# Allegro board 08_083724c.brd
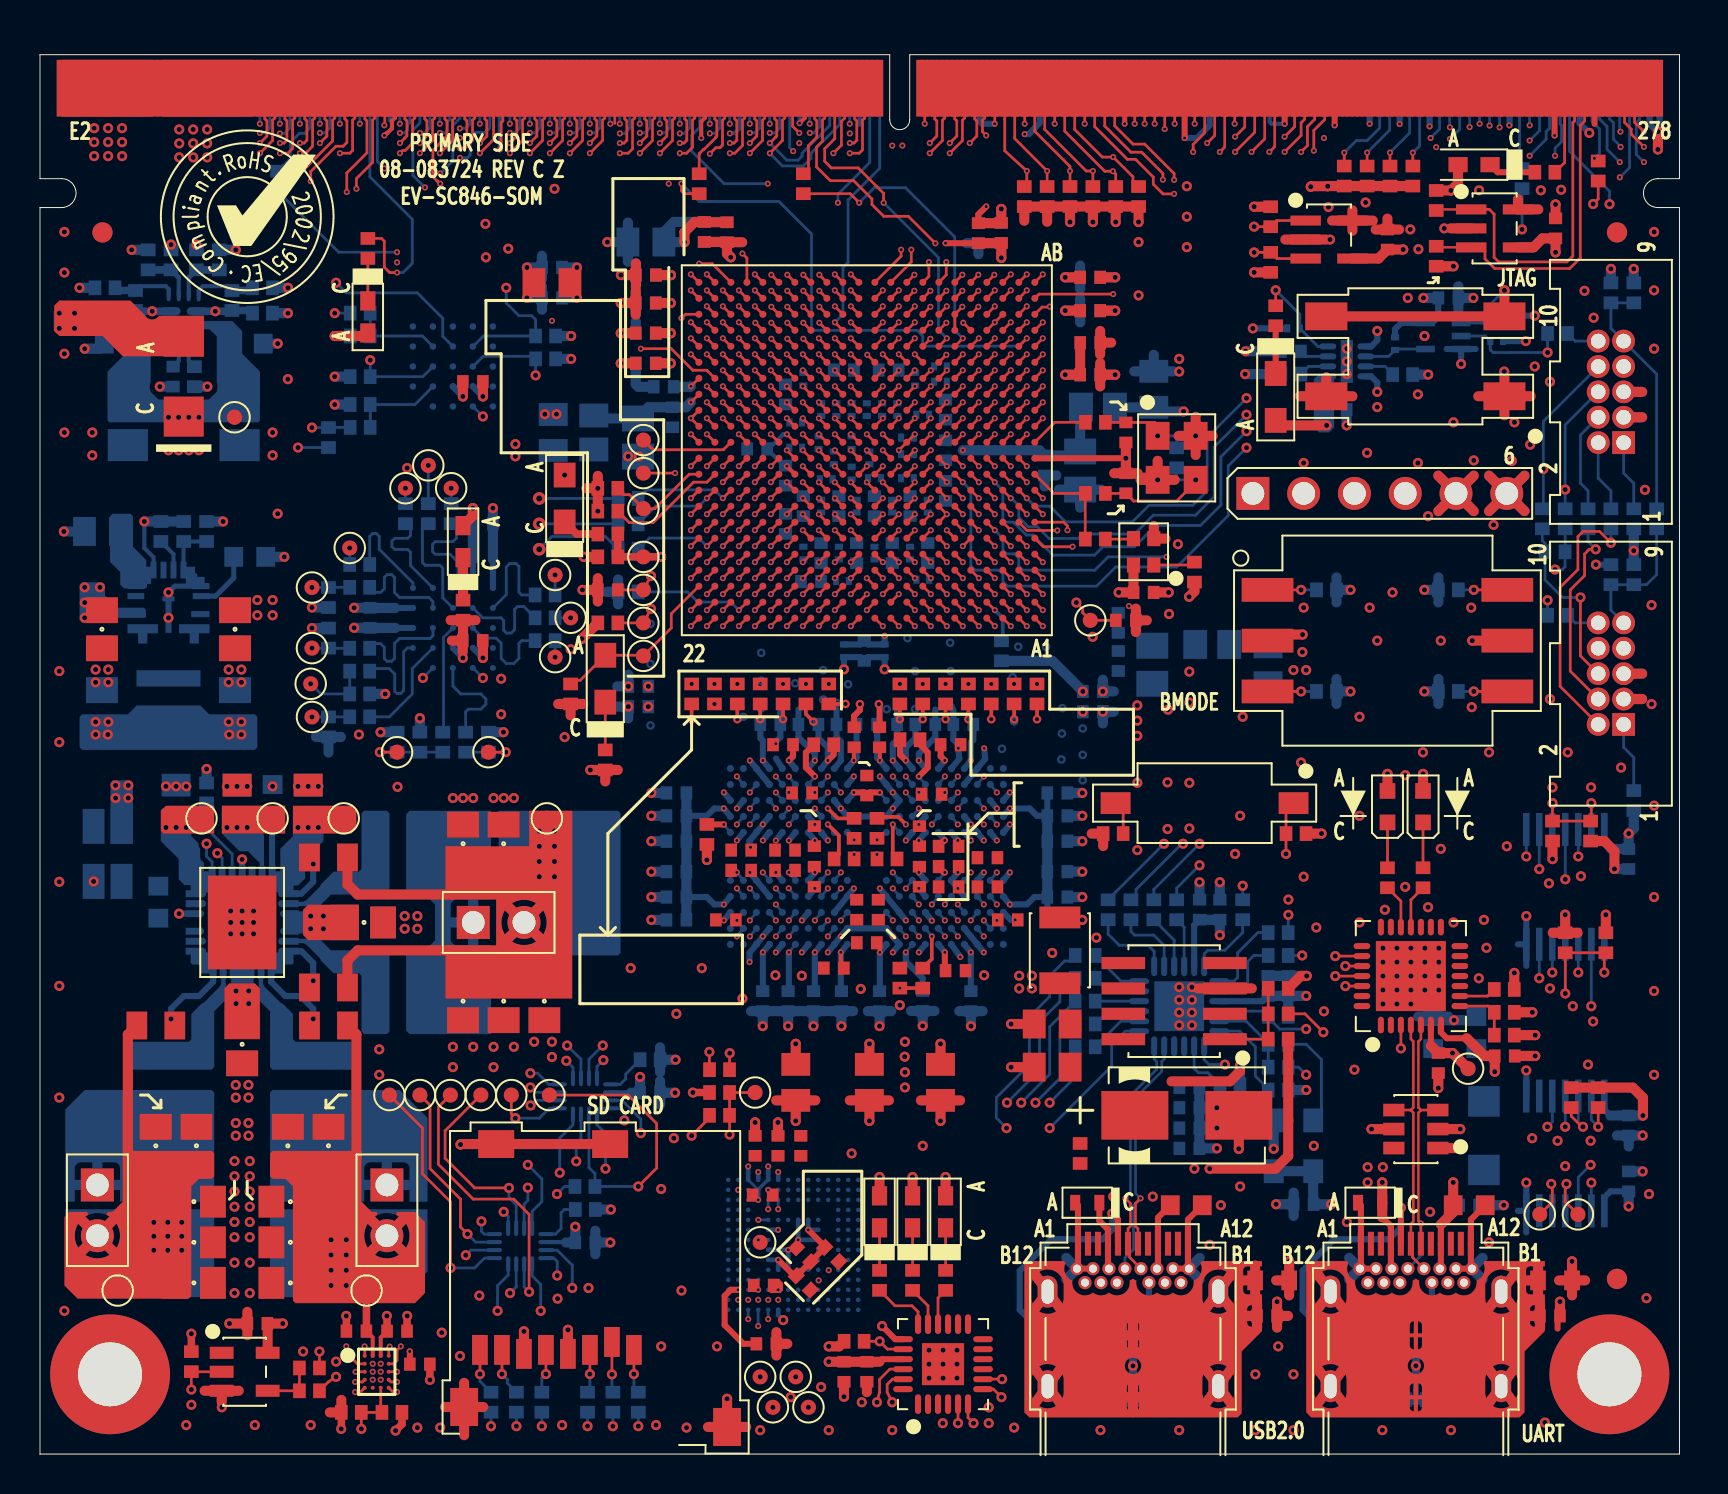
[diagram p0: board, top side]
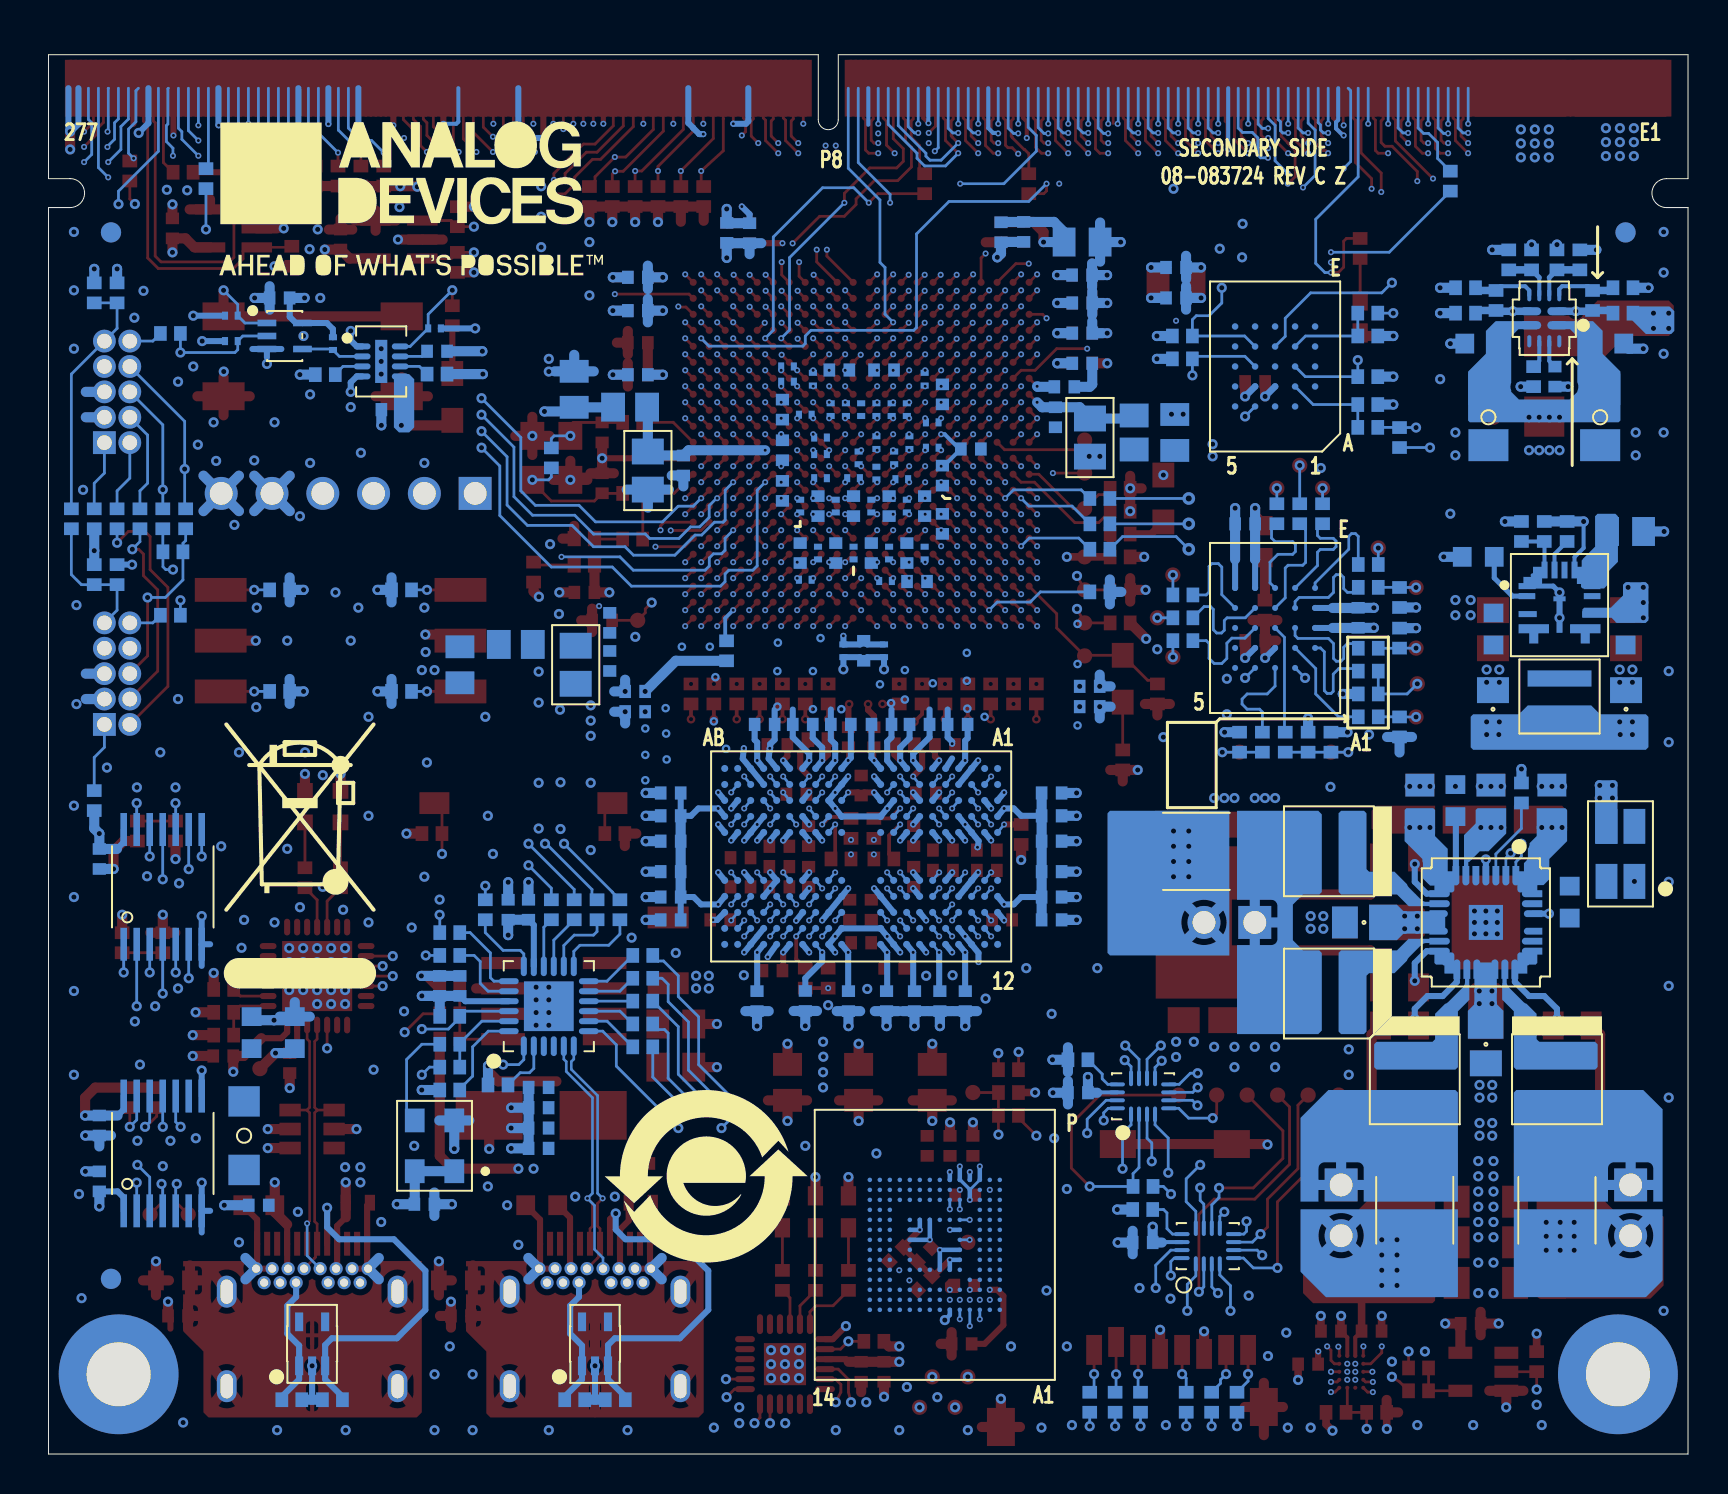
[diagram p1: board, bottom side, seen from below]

Outline 81.99 x 70 mm; copper layers: TOP, L2_GND, L3_SIG1, L4_GND, L5_SIG2, L6_PWR1, L7_PWR2, L8_SIG3, L9_GND, L10_SIG4, L11_GND, BOTTOM. Coordinates in mm from the lower left corner of the outline.
Outline path: 0,70 42.5,70 42.5,66.75 arc(43,66.25) 43.5,66.75 43.5,70 81.99,70 81.99,63.8 80.91,63.8 arc(80.19,63.08) 80.91,62.36 81.99,62.36 81.99,0 0,0 0,62.36 1.08,62.36 arc(1.8,63.08) 1.08,63.8 0,63.8 0,70

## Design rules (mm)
constraint set DEFAULT: min track width 0.14
net group _N89: nets _N89 _N102
net group ADDR-CMD-CLKA: nets CK_T_A CS1_A
net group ADDR_CMD-CLKB: nets CK_T_B CS1_B
net group DP_USB: nets USB_DM USB_DP
net group EMSI0_CLK: nets EMSI0_CLK EMSI0_CLK_X
net group PB_12/TM0_TMR5/SPI5_CLK/PWM0_DH: nets PB_12/TM0_TMR5/SPI5_CLK/PWM0__1 PB_12/TM0_TMR5/SPI5_CLK/PWM0_DH
net group PC_04/SPI2_CLK/TM0_ACLK1: nets PC_04/SPI2_CLK/TM0_ACLK1 PC_04/SPI2_CLK/TM0_ACLK1_X
net group PC_09/SPI0_CLK: nets PC_09/SPI0_CLK PC_09/SPI0_CLK_X
net group PD_12/XSPI0_D2: nets _N562 PD_12/XSPI0_D2
net group PE_11/XSPI1_CLK*: nets _N541 PE_11/XSPI1_CLK*
net group PE_12/XSPI1_CLK/FPLL2_REF_CLK: nets _N544 PE_12/XSPI1_CLK/FPLL2_REF_CLK
net group PF_04/LP0_CLK/FPLL_REF_CLK: nets PF_04/LP0_CLK/FPLL_REF_CLK PF_04/LP0_CLK/FPLL_REF_CLK_X
net group PF_10/LP1_CLK: nets PF_10/LP1_CLK PF_10/LP1_CLK_X
net group PH_10/USB0_STP: nets PH_10/USB0_STP UNNAMED_7_ICUSB331X_I85_STP
net group PH_11/USB0_D7: nets PH_11/USB0_D7 UNNAMED_7_ICUSB331X_I85_DATA7
net group PH_12/USB0_D6: nets PH_12/USB0_D6 UNNAMED_7_ICUSB331X_I85_DATA6
net group PH_13/USB0_D5: nets PH_13/USB0_D5 UNNAMED_7_ICUSB331X_I85_DATA5
net group PH_14/USB0_D4: nets PH_14/USB0_D4 UNNAMED_7_ICUSB331X_I85_DATA4
net group PH_15/USB0_NXT: nets PH_15/USB0_NXT UNNAMED_7_ICUSB331X_I85_NXT
net group PI_00/USB0_DIR: nets PI_00/USB0_DIR UNNAMED_7_ICUSB331X_I85_DIR
net group PI_01/USB0_D3: nets PI_01/USB0_D3 UNNAMED_7_ICUSB331X_I85_DATA3
net group PI_02/USB0_D2: nets PI_02/USB0_D2 UNNAMED_7_ICUSB331X_I85_DATA2
net group PI_03/USB0_D1: nets PI_03/USB0_D1 UNNAMED_7_ICUSB331X_I85_DATA1
net group PI_04/USB0_D0: nets PI_04/USB0_D0 UNNAMED_7_ICUSB331X_I85_DATA0
net group USB_PHY: nets USB_PHY_DM USB_PHY_DP
net group USB_PHY_VBUS_EN: nets UNNAMED_7_ICMIC20X5_I8_EN USB_PHY_VBUS_EN
net group CLKA-STB: nets CK_C_A DQS0_C_A DQS1_C_A
net group CLKB-STB: nets CK_C_B DQS0_C_B DQS1_C_B
net group EMSI0_RST*: nets _N244 EMSI0_RST* SYS_HWRST*
net group GRP_A0: nets DMI0_A DQ0_A DQ1_A DQ2_A DQ3_A DQ4_A DQ5_A DQ6_A DQ7_A DQS0_T_A
net group GRP_A1: nets DMI1_A DQ8_A DQ9_A DQ10_A DQ11_A DQ12_A DQ13_A DQ14_A DQ15_A DQS1_T_A
net group GRP_B0: nets DMI0_B DQ0_B DQ1_B DQ2_B DQ3_B DQ4_B DQ5_B DQ6_B DQ7_B DQS0_T_B
net group GRP_B1: nets DMI1_B DQ8_B DQ9_B DQ10_B DQ13_B DQ14_B DQ15_B DQS1_T_B
net group PC_15/SPI1_CLK/TRACE0_CLK/TM0_A: nets _N82 PC_15/SPI1_CLK/TRACE0_CLK/TM0_1 PC_15/SPI1_CLK/TRACE0_CLK/TM0_A
net group PD_14/XSPI0_CLK/TM0_ACLK4: nets _N558 PD_14/XSPI0_CLK/TM0_ACLK4 PD_14/XSPI0_CLK/TM0_ACLK4_X
net group SYS_CLKIN0: nets _N15 _N16 _N410 SYS_CLKIN0 SYS_XTAL0
net group USB_PHY_REFCLK: nets PI_05/USB0_CLK UNNAMED_7_RES_I185_N1 USB_PHY_CLKOUT USB_PHY_REFCLK
net group USB_PHY_VBUS: nets UNNAMED_7_ICUSB331X_I85_VBUS

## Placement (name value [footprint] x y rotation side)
C1  0.1uF  [C0402]  45.79 24.18 180 top
C2  0.1uF  [C0402]  43.98 28.88 270 top
C3  0.1uF  [C0402]  37.41 22.66 90 bottom
C4  0.1uF  [C0402]  38.72 28.88 270 top
C5  10uF  [C0805H55]  41.48 18.59 270 top
C6  0.1uF  [C0402]  43.98 30.91 90 top
C7  0.1uF  [C0402]  45.54 35.48 180 top
C8  0.1uF  [C0402]  37.16 35.48 0 top
C9  0.1uF  [C0402]  38.72 30.91 90 top
C10  0.1uF  [C0402]  48.4 26.72 180 top
C11  0.1uF  [C0402]  41.35 25.58 0 top
C12  0.1uF  [C0402]  45.44 30.4 180 top
C13  0.1uF  [C0402]  44.59 33.01 0 top
C14  10uF  [C0805H55]  37.8 18.59 270 top
C15  0.1uF  [C0402]  47.38 28.37 180 top
C16  0.1uF  [C0402]  41.99 35.86 270 top
C17  0.1uF  [C0402]  39.7 24.31 0 top
C18  0.1uF  [C0402]  40.72 35.86 270 top
C19  0.1uF  [C0402]  38.11 33.07 180 top
C20  0.1uF  [C0402]  45.44 28.37 180 top
C21  0.1uF  [C0402]  38.43 36.5 0 bottom
C22  0.1uF  [C0402]  40.34 36.5 0 bottom
C23  0.1uF  [C0402]  42.37 36.5 180 bottom
C24  27pF  [C0402]  54.31 48.56 90 top
C25  27pF  [C0402]  54.31 51.1 270 top
C26  10uF  [C0805H53]  52.02 49.2 270 bottom
C27  0.1uF  [C0402]  50.24 49.45 270 bottom
C28  10uF  [C0805H53]  29.91 50.85 270 bottom
C29  0.1uF  [C0402]  31.64 51.87 270 bottom
C30  10uF  [C0805H53]  55.63 39.48 270 bottom
C31  0.1uF  [C0402]  53.92 39.67 270 bottom
C32  0.1uF  [C0402]  10.87 6.53 0 top
C33  0.1uF  [C0402]  28.4 43.23 0 top
C34  0.47uF  [C0402]  30.29 57.58 180 bottom
C35  1uF  [C0402]  29.92 38.4 180 bottom
C36  1uF  [C0402]  52.65 38.15 0 bottom
C37  0.1uF  [C0402]  54.31 41.71 180 top
C38  0.22uF  [C0201]  44.4 47.42 90 bottom
C39  0.22uF  [C0201]  42.62 47.42 90 bottom
C40  0.1uF  [C0402]  43.51 47.42 90 bottom
C41  0.1uF  [C0402]  41.73 47.42 90 bottom
C42  0.22uF  [C0201]  40.84 47.42 90 bottom
C43  0.22uF  [C0201]  39.07 47.42 90 bottom
C44  0.22uF  [C0201]  41.73 45.07 90 bottom
C45  0.22uF  [C0201]  38.18 45.07 90 bottom
C46  0.22uF  [C0201]  42.24 40.18 270 bottom
C47  0.22uF  [C0201]  44.15 43.74 0 bottom
C48  0.22uF  [C0201]  40.13 43.68 0 bottom
C49  0.22uF  [C0201]  40.21 40.18 270 bottom
C50  0.1uF  [C0402]  44.27 36.5 180 bottom
C51  0.1uF  [C0402]  46.18 36.5 0 bottom
C52  0.1uF  [C0402]  50.88 33.07 180 bottom
C53  0.1UF  [C0402]  41.35 4.11 270 top
C54  0.1uF  [C0402]  21.64 40.69 0 top
C55  0.01UF  [C0402]  40.21 4.11 270 top
C56  0.1uF  [C0402]  16.5 41.83 90 bottom
C57  0.1uF  [C0402]  22.15 46.53 180 bottom
C58  0.1uF  [C0402]  21.65 53.64 0 top
C59  0.1UF  [C0402]  30.51 18.07 0 bottom
C60  0.1UF  [C0402]  27.27 10.58 0 bottom
C61  0.1uF  [C0402]  17.86 6.15 180 top
C62  0.1uF  [C0402]  15.82 6.15 0 top
C63  1uF  [C0402]  38.19 9.97 135 top
C64  1uF  [C0402]  36.33 5.51 180 top
C65  0.1uF  [C0402]  39.6 9.98 135 top
C66  2.2uF  [C0402]  19 4.5 0 top
C67  0.1uF  [C0402]  38.18 8.56 135 top
C68  0.1uF  [C0402]  36.2 8.43 0 top
C69  0.1uF  [C0402]  35.76 15.42 270 top
C70  0.1uF  [C0402]  36.14 12.95 180 top
C71  0.1uF  [C0402]  36.91 15.42 270 top
C72  1uF  [C0402]  38.05 15.42 90 top
C86  0.1uF  [C0402]  71.48 12.45 0 bottom
C87  0.01uF  [C0402]  79.45 29.77 270 bottom
C88  4.7uF  [C0603]  71.83 21.08 90 bottom
C89  0.1uF  [C0402]  73.25 19.91 0 top
C90  0.1uF  [C0402]  79.45 13.64 90 bottom
C91  0.1uF  [C0402]  79.45 16.43 270 bottom
C92  4.7uF  [C0603]  69.67 21.08 90 bottom
C93  0.1uF  [C0402]  69.93 19.56 270 top
C94  4.7uF  [C0603]  71.48 12.45 0 top
C95  0.01uF  [C0402]  75.51 6.91 0 top
C96  0.1UF  [C0402]  75.79 61.32 90 top
C97  4.7uF  [C0805H60]  3.1 41.26 270 top
C98  0.1uF  [C0402]  50.88 31.93 180 bottom
C99  0.22uF  [C0201]  39.95 45.07 90 bottom
C100  0.1uF  [C0402]  50.88 30.66 180 bottom
C101  0.1uF  [C0402]  50.88 26.72 180 bottom
C102  0.1uF  [C0402]  50.88 27.86 180 bottom
C103  0.1uF  [C0402]  50.88 29.13 180 bottom
C104  0.1uF  [C0402]  45.44 29.39 180 top
C105  0.22uF  [C0201]  43.51 45.07 90 bottom
C106  0.1uF  [C0402]  39.95 47.42 90 bottom
C107  4.7uF  [C0805H60]  9.75 41.26 270 top
C108  0.1uF  [C0402]  41.92 27.23 270 top
C109  0.1uF  [C0402]  38.18 47.42 90 bottom
C110  0.1uF  [C0402]  42.62 45.07 90 bottom
C111  0.1uF  [C0402]  39.07 45.07 90 bottom
C112  0.1uF  [C0402]  47.38 29.83 180 top
C113  0.1uF  [C0402]  29.92 37.39 180 bottom
C114  0.1uF  [C0402]  37.26 30.21 0 top
C115  0.1uF  [C0402]  41.22 40.18 270 bottom
C116  0.1uF  [C0402]  38.56 43.65 180 bottom
C117  0.1uF  [C0402]  41.35 33.44 270 top
C118  0.1uF  [C0402]  35.06 29.2 180 top
C119  22UF  [C0805H60]  3.1 37.26 270 bottom
C120  0.1uF  [C0402]  52.65 37.13 0 bottom
C121  22UF  [C0805H60]  9.75 37.26 270 bottom
C122  0.1uF  [C0402]  40.84 45.07 90 bottom
C123  10uF  [C0805H55]  9.86 32.56 90 top
C124  10uF  [C0805H55]  9.86 32.56 90 bottom
C125  0.01uF  [C0402]  70.43 57.84 0 bottom
C126  1uF  [C0603]  11.63 32.69 90 bottom
C127  2.2NF  [C0402]  62.56 55.17 180 bottom
C128  4.7uF  [C1206H71]  4.39 51.87 270 bottom
C129  0.1uF  [C0603]  4.01 55.55 180 bottom
C130  0.1uF  [C0402]  44.4 45.07 90 bottom
C131  0.1uF  [C0402]  45.29 52.25 270 bottom
C132  0.1uF  [C0402]  45.29 48.18 270 bottom
C133  0.1uF  [C0402]  37.29 53.01 90 bottom
C134  0.1uF  [C0402]  37.29 46.53 270 bottom
C135  4.7uF  [C1206H71]  9.98 51.87 270 bottom
C136  0.1uF  [C0603]  10.36 55.55 0 bottom
C137  0.01uF  [C0402]  64.85 52.25 0 bottom
C138  10uF  [C0805H55]  13.41 32.56 90 top
C139  4.7uF  [C0805H60]  16.21 26.59 0 bottom
C140  10uF  [C0805H55]  6.81 32.56 90 bottom
C141  4.7uF  [C0805H60]  16.21 26.59 0 top
C142  4.7uF  [C0805H60]  10.11 20.5 270 bottom
C143  4.7uF  [C0805H60]  10.11 20.5 270 top
C144  22UF  [C0805H60]  21.16 22.66 270 top
C145  0.1uF  [C0402]  35.06 30.21 180 top
C146  10uF  [C0805H55]  45.03 18.59 270 top
C147  0.1uF  [C0402]  34.3 26.72 0 top
C148  0.1uF  [C0402]  40.84 27.23 270 top
C149  0.1uF  [C0402]  37.26 29.2 0 top
C150  0.1uF  [C0402]  46.56 22.66 90 bottom
C151  0.1uF  [C0402]  44.15 22.66 90 bottom
C152  0.1uF  [C0402]  41.99 22.66 90 bottom
C153  0.1uF  [C0402]  40.08 22.66 90 bottom
C154  0.1uF  [C0402]  38.68 22.66 90 bottom
C155  0.1uF  [C0402]  36.14 22.66 90 bottom
C156  0.1uF  [C0402]  31.83 26.72 0 bottom
C157  0.1uF  [C0402]  31.83 27.86 0 bottom
C158  0.1uF  [C0402]  31.83 29.13 0 bottom
C159  0.1uF  [C0402]  31.83 30.66 0 bottom
C160  0.1uF  [C0402]  31.83 31.93 0 bottom
C161  0.1uF  [C0402]  31.83 33.07 0 bottom
C162  0.1uF  [C0402]  36.53 36.5 180 bottom
C163  0.1uF  [C0402]  40.21 54.23 180 bottom
C164  10uF  [C0805H55]  55.7 53.26 90 bottom
C165  10uF  [C0805H55]  61.42 39.48 270 bottom
C166  10uF  [C0805H55]  25.67 51.1 90 bottom
C167  0.47uF  [C0402]  45.29 50.22 270 bottom
C168  0.47uF  [C0402]  37.29 48.95 270 bottom
C169  0.47uF  [C0402]  42.44 54.23 180 bottom
C170  0.47uF  [C0402]  35.86 50.28 180 bottom
C171  0.47uF  [C0402]  31.19 53.39 180 bottom
C172  0.22uF  [C0201]  41.35 52.25 270 bottom
C173  0.22uF  [C0201]  45.03 54.41 0 bottom
C174  0.22uF  [C0201]  38.18 53.77 90 bottom
C175  0.22uF  [C0201]  40.59 52.25 270 bottom
C176  0.22uF  [C0201]  39.83 52.25 270 bottom
C177  0.22uF  [C0201]  39.07 52.25 270 bottom
C178  0.22uF  [C0201]  38.94 50.6 270 bottom
C179  0.22uF  [C0201]  39.7 49.83 90 bottom
C180  0.22uF  [C0201]  39.32 48.77 0 bottom
C181  0.22uF  [C0201]  37.8 51.61 180 bottom
C182  0.22uF  [C0201]  37.8 50.34 180 bottom
C183  0.22uF  [C0201]  40.59 50.6 270 bottom
C184  0.1uF  [C0402]  33.22 61.14 270 top
C185  0.1uF  [C0402]  52.52 58.87 180 top
C186  0.1uF  [C0402]  52.52 57.2 180 top
C187  0.1uF  [C0402]  34.36 61.12 270 top
C188  0.1uF  [C0402]  52.52 53.99 0 top
C189  0.1uF  [C0402]  48.07 61.09 270 top
C190  0.1uF  [C0402]  46.93 61.07 270 top
C191  0.1uF  [C0402]  52.52 55.6 0 top
C192  0.1uF  [C0402]  30.29 54.57 180 top
C193  0.1uF  [C0402]  30.29 56.07 180 top
C194  0.1uF  [C0402]  30.29 57.58 180 top
C195  0.1uF  [C0402]  25.6 59.36 180 bottom
C196  1uF  [C0402]  30.3 58.98 180 bottom
C197  1uF  [C0402]  25.6 57.84 180 bottom
C198  10uF  [C0805H55]  30.3 60.63 180 bottom
C199  10uF  [C0805H55]  25.6 58.6 180 top
C200  0.47uF  [C0402]  33.22 61.14 270 bottom
C201  0.47uF  [C0402]  52.52 58.87 180 bottom
C202  0.47uF  [C0402]  52.52 57.2 180 bottom
C203  0.47uF  [C0402]  34.36 61.12 270 bottom
C204  0.47uF  [C0402]  52.52 53.99 0 bottom
C205  0.47uF  [C0402]  46.93 61.07 270 bottom
C206  0.47uF  [C0402]  30.3 58.98 180 top
C207  0.47uF  [C0402]  48.07 61.09 270 bottom
C208  0.47uF  [C0402]  30.29 54.57 180 bottom
C209  0.47uF  [C0402]  30.29 56.07 180 bottom
C210  0.01uF  [C0201]  45.03 53.64 0 bottom
C211  0.01uF  [C0201]  41.48 49.83 90 bottom
C212  0.01uF  [C0201]  40.59 49.07 90 bottom
C213  0.01uF  [C0201]  41.73 48.82 0 bottom
C214  0.01uF  [C0201]  43.38 48.82 180 bottom
C215  0.01uF  [C0201]  43.38 50.03 0 bottom
C216  0.01uF  [C0201]  43.38 50.85 180 bottom
C217  0.01uF  [C0201]  44.15 51.99 180 bottom
C218  0.01uF  [C0201]  42.11 52.25 270 bottom
C219  0.01uF  [C0201]  42.88 52.25 270 bottom
C220  0.01uF  [C0201]  43.76 53.77 90 bottom
C221  22UF  [C0805H60]  25.22 22.66 270 top
C222  22UF  [C0805H60]  23.19 30.53 90 top
C223  22UF  [C0805H60]  23.19 22.66 270 top
C224  22UF  [C0805H60]  21.16 30.53 90 top
C225  22UF  [C0805H60]  7.7 10.59 0 top
C226  22UF  [C0805H60]  12.52 12.62 180 top
C227  22UF  [C0805H60]  7.7 12.62 0 top
C228  22UF  [C0805H60]  12.4 15.42 90 top
C229  22UF  [C0805H60]  5.79 15.42 90 top
C230  22UF  [C0805H60]  12.52 10.59 180 top
C231  22UF  [C0805H60]  7.82 15.42 90 top
C232  22UF  [C0805H60]  12.52 8.56 180 top
C233  22UF  [C0805H60]  7.7 8.56 0 top
C234  10uF  [C0805H55]  13.41 32.56 90 bottom
C235  1uF  [C0603]  5.92 27.61 270 bottom
C236  22UF  [C0805H60]  14.43 15.42 90 top
C237  0.1uF  [C0603]  10.49 44.88 0 bottom
C238  2.2uF  [C0805]  3.12 46.15 180 bottom
C239  1uF  [C0603]  9.73 41.27 270 bottom
C240  1uF  [C0603]  3.12 41.27 270 bottom
C241  0.1uF  [C0402]  55.19 43.1 180 top
C242  0.1UF  [C0402]  67.39 60.76 90 top
C243  1uF  [C0805]  50.62 21.51 180 top
C244  1uF  [C0805]  50.62 19.35 180 top
C245  1uF  [C0402]  53.92 41.58 90 bottom
C246  150UF  [C7343-31-2]  57.35 16.94 0 top
C247  22uF  [C1210H106]  51 25.2 90 top
C248  0.1UF  [C0402]  57.48 16.31 0 bottom
C249  0.01UF  [C0402]  57.48 18.34 0 bottom
C250  1uF  [C0402]  6.65 53.9 270 bottom
C251  0.1UF  [C0402]  57.48 15.29 0 bottom
C252  0.01UF  [C0402]  57.48 17.32 0 bottom
C253  0.1UF  [C0402]  62.43 23.42 90 bottom
C254  0.01UF  [C0402]  61.42 23.42 90 bottom
C255  0.1UF  [C0402]  59 27.23 90 bottom
C256  0.01UF  [C0402]  57.99 27.23 90 bottom
C257  4.7uF  [C0603]  57.33 12.45 0 top
C258  0.01uF  [C0402]  61.37 6.91 0 top
C262  0.1UF  [C0402]  63.2 12.5 180 bottom
D1  ESDA6V1SC6Y  [SOT23_6-3]  68.81 16.26 90 top
D2  ESDA25W5  [SC70-5_A]  68.81 5.51 180 bottom
D3  ESDA25P35-1U1M  [DFN2_1_6X1]  66.52 12.57 180 top
D6  ESDA25W5  [SC70-5_A]  54.66 5.51 180 bottom
D7  RBR5L30BDDTE25  [DO214ACH87]  7.19 53.9 90 top
D8  ESDA25P35-1U1M  [DFN2_1_6X1]  52.37 12.57 180 top
DS1  SML-LX0805SRC-TR  [LED0805_A]  26.24 47.8 90 top
DS2  5988E30107F  [LED0603]  41.99 12.12 90 top
DS3  5988E30107F  [LED0603]  43.64 12.12 90 top
DS4  5988E30107F  [LED0603]  45.29 12.12 90 top
DS5  5988E30107F  [LED0603]  16.4 56.88 270 top
DS6  5988E30107F  [LED0603]  21.16 45.64 90 top
DS7  LY L296-Q2R2-26-Z  [LED0603-2]  69.17 32.39 90 top
DS8  LY L296-Q2R2-26-Z  [LED0603-2]  67.39 32.39 90 top
DS9  5988E30107F  [LED0603]  71.72 64.5 180 top
DS10  SML-LX0805SRC-TR  [LED0805_A]  28.27 38.79 90 top
DS11  SML-LX0805SRC-TR  [LED0805_A]  61.8 52.88 270 top
E1  600OHM  [L1206]  72.21 15.93 90 bottom
E2  100OHM AT 100MHZ  [L0805]  58.62 40.5 0 bottom
E3  100OHM AT 100MHZ  [L0805]  52.91 52.37 0 bottom
E4  100OHM AT 100MHZ  [L0805]  27.7 51.1 270 bottom
JP1  0  [R0402]  75.9 56.06 0 bottom
JP2  0  [R0402]  79.71 46.79 90 bottom
JP3  0  [R0402]  76.28 46.79 90 bottom
JP4  0  [R0402]  78.56 46.79 90 bottom
JP5  0  [R0402]  77.42 46.79 90 bottom
JP6  0  [R0402]  80.85 46.79 90 bottom
JP7  0  [R0402]  75.13 46.79 90 bottom
JP8  0  [R0402]  75.77 45.14 180 bottom
L1  0.68UH  [LSML126W138H118]  6.43 37.9 270 bottom
L2  0.47UH  [LSMSQ157H122]  17.96 30.15 0 bottom
L3  1.5UH  [LSMSQ157H122]  6.55 18.75 270 bottom
L4  1.5UH  [LSMSQ157H122]  13.67 18.75 270 bottom
L5  0.47UH  [LSMSQ157H122]  17.96 23.04 0 bottom
NOREF  -  []  136.5 171.56 0 top
NOREF#2  -  []  3.51 3.99 0 top
NOREF#3  -  []  136.5 152.96 90 top
NOREF#4  -  []  0 0 0 top
NOREF#5  -  []  3.51 3.99 0 top
NOREF#6  -  []  -102.51 -164.11 0 top
NOREF#7  -  [unnamed#2]  78.49 3.99 0 top
NOREF#8  -  []  177.46 55.98 0 top
NOREF#9  -  []  65.03 171.56 0 top
NOREF#10  -  []  0 70 270 top
NOREF#11  -  []  132.9 171.57 0 top
NOREF#12  -  []  285.91 345.58 0 top
NOREF#13  -  []  136.5 156.57 0 top
NOREF#14  -  []  65.03 144.45 90 top
NOREF#15  -  []  0 62.36 0 top
NOREF#16  -  [unnamed#2]  78.87 61.11 90 top
NOREF#17  -  []  168.25 174.35 0 top
NOREF#18  -  []  0 0 0 top
NOREF#19  -  []  53.95 54.84 0 top
NOREF#20  -  []  168.25 154.03 0 top
NOREF#21  -  []  65.03 171.56 0 top
NOREF#22  -  []  -200.3 -242.85 0 top
NOREF#23  -  []  60.03 70 0 top
NOREF#24  -  []  81.99 70 180 top
NOREF#25  -  []  0 70 0 top
NOREF#26  -  [unnamed#2]  3.51 3.99 0 top
NOREF#27  -  []  79.48 -98.58 0 top
NOREF#28  -  []  81.99 0 0 top
NOREF#29  -  []  81.99 0 90 top
NOREF#30  -  []  -32.74 135.53 0 top
NOREF#31  -  []  0 70 0 top
NOREF#32  -  []  -102.51 -164.11 0 top
NOREF#33  -  []  -8.66 -88.93 0 top
NOREF#34  -  []  65.03 152.96 90 top
NOREF#35  -  [unnamed#2]  78.87 8.76 90 top
NOREF#36  -  [unnamed#2]  3.12 61.11 0 top
NOREF#37  -  []  72.23 -93.36 0 top
NOREF#38  -  []  0 70 0 top
NOREF#39  -  []  143.93 112.43 0 top
NOREF#40  -  []  -102.51 -164.11 0 top
NOREF#41  -  []  81.99 0 90 top
NOREF#42  -  []  81.99 0 90 top
NOREF#43  -  []  43.5 70 0 top
NOREF#44  -  []  -19.14 -94.32 0 top
NOREF#45  -  []  -102.51 -164.11 0 top
NOREF#46  -  []  0 0 0 top
NOREF#47  -  []  -26.83 168.28 90 top
NOREF#48  -  []  10.36 61.9 0 top
NOREF#49  -  []  63.83 62.79 180 bottom
NOREF#50  -  []  60.15 40.18 180 bottom
NOREF#51  -  [unnamed#2]  78.87 8.76 270 bottom
NOREF#52  -  [unnamed#2]  78.87 61.11 180 bottom
NOREF#53  -  []  49.1 13.89 180 bottom
NOREF#54  -  [unnamed#2]  3.12 61.11 180 bottom
P2  632723300011  [CNWURTH632723300011]  68.81 5.94 0 top
P3  632723300011  [CNWURTH632723300011]  54.66 5.94 0 top
P4  SHF-105-01-L-D-TH-TR  [CNTHMHDR2X5L500W200H215]  79.2 36.5 90 top
P5  SHF-105-01-L-D-TH-TR  [CNTHMHDR2X5L500W200H215]  79.2 50.6 90 top
P6  693071010811  [CNWURTH693071010811]  27.76 8.31 0 top
P7  TSW-102-08-G-S  [CNSAMTEC1X2H330LD36]  22.94 26.59 0 top
P8  NCFINGER274P_E4P  [FINGER274P_E4P]  43 68.33 0 top
P9  TSW-102-08-G-S  [CNSAMTEC1X2H330LD36]  2.87 12.19 270 top
P10  TSW-102-08-G-S  [CNSAMTEC1X2H330LD36]  17.35 12.19 270 top
P12  TSW-106-08-G-S  [CNBERG1X6H205LD36]  60.66 48.06 0 top
R1  10K  [R0402]  64.34 43.23 0 bottom
R2  10K  [R0402]  70.43 38.15 180 bottom
R3  10K  [R0402]  64.34 38.15 0 bottom
R4  0  [R0402]  79.71 32.69 90 bottom
R5  0  [R0402]  75.9 41.96 0 bottom
R6  10K  [R0402]  70.43 43.23 180 bottom
R7  10  [R0402]  28.4 46.02 0 top
R8  10K  [R0402]  28.4 44.88 0 top
R9  10K  [R0402]  28.4 41.58 0 top
R10  10K  [R0402]  79.71 43.99 270 bottom
R11  0  [R0402]  28.4 48.31 180 top
R12  10  [R0402]  28.27 34.72 270 top
R13  10K  [R0402]  78.56 43.99 90 bottom
R14  10K  [R0402]  79.71 58.09 270 bottom
R15  10K  [R0402]  78.56 58.09 90 bottom
R16  240  [R0402]  33.35 31 90 top
R17  10K  [R0402]  40.72 5.64 0 top
R18  10K  [R0402]  14.43 40.82 270 bottom
R19  10K  [R0402]  14.43 36.37 270 bottom
R20  10K  [R0402]  22.43 35.61 270 bottom
R21  10K  [R0402]  15.99 38.02 0 bottom
R22  0  [R0402]  15.99 40.31 0 bottom
R23  0  [R0402]  15.99 36.88 0 bottom
R24  0  [R0402]  21.29 35.61 90 bottom
R25  0  [R0402]  15.99 39.17 0 bottom
R26  150  [R0402]  41.99 8.69 270 top
R27  0  [R0402]  20.14 35.61 270 bottom
R28  0  [R0402]  19.42 47.04 90 bottom
R29  0  [R0402]  25.26 41.83 0 bottom
R30  0  [R0402]  25.26 42.98 0 bottom
R31  0  [R0402]  18.28 47.04 90 bottom
R32  0  [R0402]  15.99 43.36 180 bottom
R33  0  [R0402]  25.26 40.69 0 bottom
R34  0  [R0402]  20.56 47.04 90 bottom
R35  0  [R0402]  15.99 44.5 180 bottom
R36  150  [R0402]  43.64 8.69 270 top
R37  150  [R0402]  45.29 8.69 270 top
R38  10K  [R0402]  17.86 35.61 270 bottom
R39  1.5K  [R0402]  62.81 31.04 180 top
R40  10K  [R0402]  19 35.61 90 bottom
R41  150  [R0402]  16.4 60.31 90 top
R42  150  [R0402]  21.16 42.21 270 top
R43  0  [R0402]  16.01 51.36 0 bottom
R44  10K  [R0402]  16.01 53.9 0 bottom
R45  10K  [R0402]  16.01 52.5 180 bottom
R46  10K  [R0402]  16.01 55.93 0 bottom
R47  10K  [R0402]  25.29 54.79 180 bottom
R48  10K  [R0402]  25.29 55.93 180 bottom
R49  33  [R0402]  16.01 57.07 180 bottom
R50  10K  [R0402]  30.51 19.72 0 bottom
R51  10K  [R0402]  27.27 12.23 0 bottom
R52  0  [R0402]  33.99 19.23 0 top
R53  33  [R0402]  25.1 2.59 90 bottom
R54  33  [R0402]  27.38 2.59 90 bottom
R55  33  [R0402]  23.83 2.59 90 bottom
R56  33  [R0402]  29.92 2.59 90 bottom
R57  33  [R0402]  13.47 3.16 180 top
R58  33  [R0402]  22.56 2.59 90 bottom
R59  33  [R0402]  28.65 2.59 90 bottom
R60  33  [R0402]  13.47 4.31 180 top
R61  33  [R0402]  38.18 63.55 270 top
R62  33  [R0402]  14.43 50.85 270 bottom
R63  33  [R0402]  29.41 45.26 0 bottom
R64  0  [R0402]  61.93 19.35 180 bottom
R65  33  [R0402]  52.27 24.94 0 bottom
R66  10K  [R0402]  7.57 4.62 270 top
R67  10K  [R0402]  26.54 38.02 270 top
R68  120  [R0402]  29.41 43.13 180 bottom
R81  100K  [R0402]  75.64 31.17 90 top
R82  20K  [R0402]  77.55 31.17 270 top
R83  100K  [R0402]  78.31 25.58 270 top
R84  20K  [R0402]  76.28 25.58 90 top
R85  22.1K  [R0402]  73.23 22.1 180 top
R86  47.5K  [R0402]  73.23 20.95 0 top
R87  10K  [R0402]  73.23 23.24 180 top
R88  100K  [R0402]  77.93 17.83 270 top
R89  100K  [R0402]  76.58 17.83 270 top
R90  330  [R0402]  69.17 28.83 270 top
R91  1MEG  [R0603]  75.77 8.69 0 top
R92  330  [R0402]  67.39 28.83 270 top
R93  5.1K  [R0402]  67.79 2.72 0 bottom
R94  5.1K  [R0402]  69.82 2.72 180 bottom
R95  3K  [R0402]  69.82 62.71 270 top
R96  3K  [R0402]  69.82 59.92 90 top
R97  60.4  [R0402]  44.15 23.81 90 top
R98  60.4  [R0402]  41.86 31.3 90 top
R101  10K  [R0402]  57.73 44.12 90 top
R102  150  [R0402]  75.26 64.12 0 top
R103  10K  [R0402]  61.93 23.29 0 top
R104  0.1  [R1206-4P]  3.38 30.02 90 bottom
R105  23.7K  [R0402]  8.97 59.74 90 bottom
R106  10  [R0805]  5.79 21.44 180 top
R107  10.2K  [R0402]  9.6 57.71 270 bottom
R109  10  [R0805]  14.43 21.44 0 top
R111  13.7K  [R0402]  4.78 57.71 90 bottom
R112  0.005  [R2512H35]  13.67 12.19 270 bottom
R113  10K  [R0201]  72.85 56.95 180 bottom
R114  33  [R0402]  52.78 45.77 180 top
R115  3K  [R0402]  61.54 61.9 270 top
R116  10K  [R0402]  6.05 46.15 270 bottom
R117  3K  [R0402]  61.54 59.61 90 top
R118  60.4  [R0402]  40.72 31.3 90 top
R119  10K  [R0402]  8.33 46.15 90 bottom
R120  10K  [R0402]  7.19 46.15 270 bottom
R121  60.4  [R0402]  42.36 29.77 180 top
R122  60.4  [R0402]  40.22 29.77 0 top
R123  10K  [R0201]  72.85 55.68 180 bottom
R124  10K  [R0402]  8.33 33.07 90 bottom
R125  10  [R0805]  14.43 29.84 0 top
R126  0.005  [R2512H35]  24.59 30.15 0 bottom
R127  10K  [R0201]  67.77 55.55 270 bottom
R128  0.005  [R2512H35]  6.55 12.19 270 bottom
R129  0  [R0402]  68.15 54 180 bottom
R130  0  [R0402]  62.56 54.03 180 bottom
R131  10  [R0805]  14.43 23.34 0 top
R132  3K  [R0402]  65.23 63.93 90 top
R133  3K  [R0402]  66.37 63.93 90 top
R134  3K  [R0402]  67.51 63.93 90 top
R135  3K  [R0402]  68.66 63.93 90 top
R136  3K  [R0402]  49.23 62.91 90 top
R137  3K  [R0402]  50.37 62.91 90 top
R138  3K  [R0402]  51.51 62.91 90 top
R139  3K  [R0402]  52.65 62.91 90 top
R140  3K  [R0402]  53.8 62.91 90 top
R141  3K  [R0402]  54.94 62.91 90 top
R142  0  [R0402]  52.78 48.06 180 top
R143  0  [R0402]  52.78 51.61 0 top
R144  33  [R0402]  29.41 47.8 180 bottom
R145  10K  [R0402]  14.43 42.85 90 bottom
R147  4.7K  [R0402]  43 23.81 90 top
R148  4.7K  [R0402]  43.51 35.74 180 top
R149  4.7K  [R0402]  39.19 35.48 0 top
R150  4.7K  [R0402]  48.08 40.18 90 bottom
R151  33  [R0402]  77.93 64.19 90 top
R152  33  [R0402]  74.12 63.8 90 bottom
R153  0  [R0402]  28.4 47.17 180 top
R154  10K  [R0402]  33.99 18.08 0 top
R155  10K  [R0402]  17.6 2.08 180 top
R156  10K  [R0402]  15.57 2.08 180 top
R157  0  [R0402]  33.99 16.94 0 top
R158  100K  [R0402]  56.85 49.83 270 bottom
R159  10K  [R0201]  62.69 56.31 0 bottom
R160  150  [R0402]  61.8 56.95 90 top
R163  0  [R0402]  3.25 57.07 0 bottom
R164  0  [R0402]  11.13 57.07 180 bottom
R165  23.7K  [R0402]  5.41 59.74 90 bottom
R166  5K  [R0402]  6.55 59.74 270 bottom
R167  5K  [R0402]  7.82 59.74 270 bottom
R168  5K  [R0402]  11.13 58.34 180 bottom
R169  5K  [R0402]  3.25 58.34 0 bottom
R170  21.5K  [R0402]  7.72 53.9 90 bottom
R175  33  [R0402]  32.97 63.55 270 top
R176  33  [R0402]  27.25 13.39 0 bottom
R177  33  [R0402]  29.41 46.53 180 bottom
R178  33  [R0402]  11.89 63.68 270 bottom
R179  0  [R0402]  37.16 38.02 270 top
R180  0  [R0402]  47.57 38.02 270 top
R181  0  [R0402]  49.86 38.02 270 top
R182  0  [R0402]  46.43 38.02 270 top
R183  0  [R0402]  45.29 38.02 270 top
R184  0  [R0402]  44.15 38.02 270 top
R185  0  [R0402]  48.72 38.02 270 top
R186  0  [R0402]  43 38.02 270 top
R187  0  [R0402]  36.02 38.02 270 top
R188  0  [R0402]  34.87 38.02 270 top
R189  0  [R0402]  38.3 38.02 270 top
R190  0  [R0402]  39.45 38.02 270 top
R191  0  [R0402]  33.73 38.02 270 top
R192  0  [R0402]  32.59 38.02 270 top
R193  0  [R0402]  61.93 22.02 180 top
R194  0  [R0402]  52.27 20.37 180 bottom
R195  0  [R0402]  52.27 21.51 180 bottom
R196  0  [R0402]  52.27 22.66 180 bottom
R197  0  [R0402]  52.27 23.8 180 bottom
R198  0  [R0402]  53.42 27.23 90 bottom
R199  0  [R0402]  54.56 27.23 90 bottom
R200  0  [R0402]  55.7 27.23 90 bottom
R201  0  [R0402]  56.85 27.23 90 bottom
R202  0  [R0402]  60.15 27.23 90 bottom
R203  0  [R0402]  61.93 26.09 0 bottom
R205  0  [R0402]  61.93 24.94 180 bottom
R206  8.06K  [R0402]  61.93 18.21 0 bottom
R207  10K  [R0402]  61.93 21.89 0 bottom
R208  5.1K  [R0402]  53.64 2.72 0 bottom
R209  5.1K  [R0402]  55.68 2.72 180 bottom
R210  0  [R0402]  52.02 15.04 90 top
R211  1MEG  [R0603]  61.62 8.69 0 top
R212  1.5K  [R0402]  53.67 31.04 180 top
R217  33  [R0402]  61.93 20.5 180 bottom
R218  1K  [R0402]  59.51 18.47 180 bottom
R221  10K  [R0402]  61.93 20.75 180 top
S1  A6S-1104-H  [SWSML137W244H177]  58.24 32.56 90 top
S2  RDTAR10S1R  [SWSMSQ394H268]  67.39 40.69 270 top
S4  ADTSMW64NVTR  [SWSML248W244H185]  68.78 54.91 90 top
TP1  TESTPAD  [TPSMC30]  30.18 44.88 0 top
TP2  TESTPAD  [TPSMC30]  30.18 41.58 0 top
TP3  TESTPAD  [TPSMC30]  13.6 40.32 0 top
TP4  TESTPAD  [TPSMC30]  13.6 36.87 0 top
TP5  TESTPAD  [TPSMC30]  22.43 35.11 0 top
TP6  TESTPAD  [TPSMC30]  13.54 38.53 0 top
TP7  TESTPAD  [TPSMC30]  17.86 35.11 0 top
TP8  TESTPAD  [TPSMC30]  26.54 41.83 0 top
TP9  TESTPAD  [TPSMC30]  18.28 48.32 0 top
TP10  TESTPAD  [TPSMC30]  25.76 39.87 0 top
TP11  TESTPAD  [TPSMC30]  15.49 45.33 0 top
TP12  TESTPAD  [TPSMC30]  19.42 49.46 0 top
TP13  TESTPAD  [TPSMC30]  25.76 43.97 0 top
TP14  TESTPAD  [TPSMC30]  13.6 43.35 0 top
TP15  TESTPAD  [TPSMC30]  20.56 48.32 0 top
TP16  TESTPAD  [TPSMC30]  76.91 11.99 90 top
TP17  TESTPAD  [TPSMC30]  75.01 11.99 90 top
TP18  TESTPAD  [TPSMC30]  71.42 19.28 0 top
TP19  TESTPAD  [TPSMC30]  20.52 17.96 0 top
TP20  TESTPAD  [TPSMC30]  25.35 31.8 0 top
TP21  TESTPAD  [TPSMC30]  3.89 8.18 270 top
TP22  TESTPAD  [TPSMC30]  9.73 51.87 180 top
TP23  TESTPAD  [TPSMC30]  16.33 8.18 0 top
TP24  TESTPAD  [TPSMC30]  30.18 50.72 270 top
TP25  TESTPAD  [TPSMC30]  30.18 39.93 180 top
TP26  TESTPAD  [TPSMC30]  30.18 49.07 0 top
TP27  TESTPAD  [TPSMC30]  30.18 47.29 270 top
TP28  5016  [CNKEY5016TP]  10.11 26.59 90 top
TP29  TESTPAD  [TPSMC30]  11.63 31.8 0 top
TP30  TESTPAD  [TPSMC30]  8.08 31.8 0 top
TP31  TESTPAD  [TPSMC30]  15.19 31.8 270 top
TP32  TESTPAD  [TPSMC30]  52.53 41.71 0 top
TP33  TESTPAD  [TPSMC30]  30.18 43.23 0 top
TP34  TESTPAD  [TPSMC30]  17.48 17.96 0 top
TP35  TESTPAD  [TPSMC30]  19 17.96 0 top
TP36  TESTPAD  [TPSMC30]  22.05 17.96 0 top
TP37  TESTPAD  [TPSMC30]  36.02 3.86 0 top
TP38  TESTPAD  [TPSMC30]  36.65 2.34 0 top
TP39  TESTPAD  [TPSMC30]  37.8 3.86 0 top
TP40  TESTPAD  [TPSMC30]  38.43 2.34 0 top
TP41  TESTPAD  [TPSMC30]  23.57 17.96 0 top
TP42  TESTPAD  [TPSMC30]  25.48 17.96 0 top
TP43  TESTPAD  [TPSMC30]  36.02 10.59 0 top
TP44  TESTPAD  [TPSMC30]  35.76 18.08 0 top
U1  ADSP-SC846-BPZENG  [BGA484_18X18]  41.35 50.22 90 top
U2  MAX20406EAFLD/VY+  [FC2QFN15_F153A3FY_2]  6.43 42.47 180 bottom
U3  IS46LQ32256B-062BLA3  [BGA200_14_5X10H1_05]  41.35 29.9 0 bottom
U4  ADP5587ACPZ  [QFN24_4X4_PAD2_1X2_1]  45.16 4.5 0 top
U5  IS72WVO32M8AWO256-200HLA2  [BGA24_8X6]  20.65 41.33 90 bottom
U6  IS25WP02GG-RHLE  [TBGA24]  20.65 54.41 90 bottom
U7  TMUX1574RSVR  [QFN16_2_6X1_8_A]  27.25 17.89 180 bottom
U8  TMUX1574RSVR  [QFN16_2_6X1_8_A]  24.02 10.4 180 bottom
U9  NVT4857UKAZ  [WLCSP20-2]  16.84 4.11 270 top
U10  IS22TF16G-JCLA2  [BGA153_13X11_50]  37.67 10.46 90 bottom
U13  TXS0104EPWR  [TSSOP14]  76.28 15.04 90 bottom
U14  CP2102N-A02-GQFN28  [QFN28_5X5_PAD3_5X3_5]  68.56 23.91 0 top
U15  24AA01T-I/OT  [SOT23-5L]  72.75 61.32 270 top
U16  MAX25228AFYB/VY+  [QFN29_5X5_PAD1_66X1_7]  10.11 26.59 270 bottom
U17  24AA01T-I/OT  [SOT23-5L]  64.47 60.76 270 top
U18  74LVC1G08GW-Q100  [SOT353]  70.18 55.93 270 bottom
U19  SN74LVC1G04QDBVRQ1  [SOT23-5L-2]  10.24 4.11 270 top
U20  TPS2121RUXR  [VQFN12_2X2_5]  7.19 56.82 0 bottom
U21  LTC2916HDDB-1#TRMPBF  [DFN8_3X2_PAD2_15X0_56_05-08-1702]  65.35 54.66 270 bottom
U22  USB3317C-CP-TR  [QFN24_4X4_PAD2_5X2_5]  56.97 22.4 180 bottom
U23  MIC2025-1YM  [SO8]  56.72 22.66 90 top
U29  TC7MBL3125CFT(EL)  [TSSOP14]  76.28 28.37 90 bottom
Y1  25MEGHZ  [YSML126W98H31]  56.85 49.83 270 top
Y2  25MEGHZ  [YSML79W63H32]  55.19 45.14 90 top
Y4  26MEGHZ  [XSM4PL126W98H39]  62.69 15.42 90 bottom

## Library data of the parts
C1-C4 C6-C13 C15-C23 C27 C29 C31-C37 C40 C41 C50-C65 C67-C72 C86 C87 C89-C91 C93 C95 C96 C98 C100-C104 C106 C108-C118 C120 C122 C130-C134 C145 C147-C163 C167-C171 C184-C197 C200-C209 C241 C242 C245 C248-C256 C258 C262 = CAP: User Part Number: UPN; Tolerance: 10; alternate symbols: (C0402); tolerance: 10
C5 C14 C123 C124 C138 C140 C146 C164-C166 C198 C199 C234 = CAP: User Part Number: UPN; Tolerance: 10; alternate symbols: (C0805H55); tolerance: 10
C24 C25 C125 C137 = CAP: User Part Number: UPN; Tolerance: 5; alternate symbols: (C0402); tolerance: 5
C26 C28 C30 = CAP: Tolerance: 10; User Part Number: UPN; alternate symbols: (C0805H53); tolerance: 10
C38 C39 C42-C49 C99 C105 C172-C183 = CAP: Tolerance: 20; User Part Number: UPN; alternate symbols: (C0201); tolerance: 20
C66 C127 = CAP: User Part Number: UPN; Tolerance: 20; alternate symbols: (C0402); tolerance: 20
C88 C92 C94 C126 C129 C136 C235 C237 C239 C240 C257 = CAP: User Part Number: UPN; Tolerance: 10; alternate symbols: (C0603); tolerance: 10
C97 C107 C139 C141-C143 = CAP: Tolerance: 10; User Part Number: UPN; alternate symbols: (C0805H60); tolerance: 10
C119 C121 C144 C221-C233 C236 = CAP: Tolerance: 20; User Part Number: UPN; alternate symbols: (C0805H60); tolerance: 20
C128 C135 = CAP: Tolerance: 10; User Part Number: UPN; alternate symbols: (C1206H71); tolerance: 10
C210-C220 = CAP: Tolerance: 10; User Part Number: UPN; alternate symbols: (C0201); tolerance: 10
C238 C243 C244 = CAP: User Part Number: UPN; Tolerance: 10; alternate symbols: (C0805); tolerance: 10
C246 = CAPP: Tolerance: 20; User Part Number: UPN; alternate symbols: (C7343-31-2); tolerance: 20
C247 = CAP: Tolerance: 10; User Part Number: UPN; alternate symbols: (C1210H106); tolerance: 10
D1 = DIOTVS6P_V9: User Part Number: UPN; Tolerance: N/A; alternate symbols: (SOT23_6-3); tolerance: N/A
D2 D6 = DIOTVS5P_V4: User Part Number: UPN; Tolerance: N/A; alternate symbols: (SC70-5_A); tolerance: N/A
D3 D8 = DIOZNR: User Part Number: UPN; Tolerance: N/A; alternate symbols: (DFN2_1_6X1); tolerance: N/A
D7 = DIOSCHOTTKY: User Part Number: UPN; Tolerance: N/A; alternate symbols: (DO214ACH87); tolerance: N/A
DS1 DS10 DS11 = DIOLED: Tolerance: N/A; User Part Number: UPN; alternate symbols: (LED0805_A); tolerance: N/A
DS2-DS6 DS9 = DIOLED: Tolerance: N/A; User Part Number: UPN; alternate symbols: (LED0603); tolerance: N/A
DS7 DS8 = DIOLED: Tolerance: N/A; User Part Number: UPN; alternate symbols: (LED0603-2); tolerance: N/A
E1 = FERRITE: Tolerance: 25; User Part Number: UPN; alternate symbols: (L1206); tolerance: 25
E2-E4 = FERRITE: User Part Number: UPN; Tolerance: 25; alternate symbols: (L0805); tolerance: 25
JP1-JP8 R4 R5 = RESJMPRSHRT: User Part Number: UPN; Tolerance: JUMPER; alternate symbols: (R0402); tolerance: JUMPER
L1 = IND: Tolerance: 20; User Part Number: UPN; alternate symbols: (LSML126W138H118); tolerance: 20
L2-L5 = IND: User Part Number: UPN; Tolerance: 20; alternate symbols: (LSMSQ157H122); tolerance: 20
P2 P3 = CN24PAB_2GND_6SHLD: Tolerance: N/A; User Part Number: UPN; alternate symbols: (CNWURTH632723300011); tolerance: N/A
P4 P5 = CN10P: User Part Number: UPN; Tolerance: N/A; alternate symbols: (CNTHMHDR2X5L500W200H215); tolerance: N/A
P6 = CN10P_V4: Tolerance: N/A; User Part Number: UPN; alternate symbols: (CNWURTH693071010811); tolerance: N/A
P7 P9 P10 = CN2P: User Part Number: UPN; Tolerance: N/A; alternate symbols: (CNSAMTEC1X2H330LD36); tolerance: N/A
P8 = NCFINGER274P_E4P: User Part Number: UPN; Tolerance: N/A; alternate symbols: (FINGER274P_E4P); tolerance: N/A
P12 = CN6P: User Part Number: UPN; Tolerance: N/A; alternate symbols: (CNBERG1X6H205LD36); tolerance: N/A
R1-R3 R6-R10 R12-R15 R17-R21 R38 R40 R44-R48 R50 R51 R66 R67 R82 R84-R87 R90 R92 R101 R105 R111 R116 R119 R120 R145 R148-R150 R154-R156 R165-R170 R206 R217 R218 = RES: User Part Number: UPN; Tolerance: 1; alternate symbols: (R0402); tolerance: 1
R11 R22-R25 R27-R35 R43 R52 R64 R129 R130 R142 R143 R153 R157 R163 R164 R179-R203 R205 R210 = RES: User Part Number: UPN; Tolerance: JUMPER; alternate symbols: (R0402); tolerance: JUMPER
R16 R68 R93 R94 R107 R208 R209 = RES: User Part Number: UPN; Tolerance: 0.1; alternate symbols: (R0402); tolerance: 0.1
R26 R36 R37 R39 R41 R42 R49 R53-R63 R65 R81 R83 R88 R89 R95 R96 R102 R103 R114 R115 R117 R124 R132-R141 R144 R151 R152 R158 R160 R175-R178 R207 R212 R221 = RES: User Part Number: UPN; Tolerance: 5; alternate symbols: (R0402); tolerance: 5
R91 R211 = RES: User Part Number: UPN; Tolerance: 1; alternate symbols: (R0603); tolerance: 1
R97 R98 R118 R121 R122 = RES: User Part Number: UPN; Tolerance: 1; alternate symbols: (R0402); tolerance: 1; signal model: RES_SM-60.4_E003769_1/10W_1_R0B_60.4
R104 = RES4PKEL_V6: User Part Number: UPN; Tolerance: 0.25; alternate symbols: (R1206-4P); tolerance: 0.25
R106 R109 R125 R131 = RES: User Part Number: UPN; Tolerance: 1; alternate symbols: (R0805); tolerance: 1
R112 R126 R128 = RES: User Part Number: UPN; Tolerance: 1; alternate symbols: (R2512H35); tolerance: 1
R113 R123 R127 R159 = RES: Tolerance: 1; User Part Number: UPN; alternate symbols: (R0201); tolerance: 1
R147 = RES: User Part Number: UPN; Tolerance: 1; alternate symbols: (R0402); tolerance: 1; signal model: RES_SM-4.7K_E008190_1/10W_1_R0B_4.7K
S1 = SWSPST2PIN_V4: User Part Number: UPN; Tolerance: N/A; alternate symbols: (SWSML137W244H177); tolerance: N/A
S2 = SWBCDROTARY6P: User Part Number: UPN; Tolerance: N/A; alternate symbols: (SWSMSQ394H268); tolerance: N/A
S4 = SWSPST4PIN_B: User Part Number: UPN; Tolerance: N/A; alternate symbols: (SWSML248W244H185); tolerance: N/A
TP1-TP27 TP29-TP44 = NCTESTPAD: Tolerance: N/A; User Part Number: UPN; alternate symbols: (TPSMC30); tolerance: N/A
TP28 = CNTP1P: Tolerance: N/A; User Part Number: UPN; alternate symbols: (CNKEY5016TP); tolerance: N/A
U1 = ADSPSC846: User Part Number: UPN; Tolerance: N/A; alternate symbols: (BGA484_18X18); tolerance: N/A
U2 = ADMAX2040X_V2: User Part Number: UPN; Tolerance: N/A; alternate symbols: (FC2QFN15_F153A3FY_2); tolerance: N/A
U3 = ICIS46LQ2256B_0XXBLXX: Tolerance: N/A; User Part Number: UPN; alternate symbols: (BGA200_14_5X10H1_05); tolerance: N/A
U4 = ADP5587: Tolerance: N/A; User Part Number: UPN; alternate symbols: (QFN24_4X4_PAD2_1X2_1); tolerance: N/A
U5 = ICIS7XWVOXXM8: Tolerance: N/A; User Part Number: UPN; alternate symbols: (BGA24_8X6); tolerance: N/A
U6 = ICIS25XP02GG: User Part Number: UPN; Tolerance: N/A; alternate symbols: (TBGA24); tolerance: N/A
U7 U8 = ICTMUX1574: User Part Number: UPN; Tolerance: N/A; alternate symbols: (QFN16_2_6X1_8_A); tolerance: N/A
U9 = ICNVT4857: Tolerance: N/A; User Part Number: UPN; alternate symbols: (WLCSP20-2); tolerance: N/A
U10 = IS22TF16G: User Part Number: UPN; Tolerance: N/A; alternate symbols: (BGA153_13X11_50); tolerance: N/A
U13 = ICTXS0104E: Tolerance: N/A; User Part Number: ***; alternate symbols: (TSSOP14); tolerance: N/A
U14 = ICCP2102NA: User Part Number: UPN; Tolerance: N/A; alternate symbols: (QFN28_5X5_PAD3_5X3_5); tolerance: N/A
U15 U17 = IC24XX01: User Part Number: UPN; Tolerance: N/A; alternate symbols: (SOT23-5L); tolerance: N/A
U16 = ADMAX25228: Tolerance: N/A; User Part Number: UPN; alternate symbols: (QFN29_5X5_PAD1_66X1_7); tolerance: N/A
U18 = 7408_V6: User Part Number: UPN; Tolerance: N/A; alternate symbols: (SOT353); tolerance: N/A
U19 = 741G04: User Part Number: UPN; Tolerance: N/A; alternate symbols: (SOT23-5L-2); tolerance: N/A
U20 = ICTPS2121: User Part Number: UPN; Tolerance: N/A; alternate symbols: (VQFN12_2X2_5); tolerance: N/A
U21 = ADLTC291X_V2: User Part Number: UPN; Tolerance: N/A; alternate symbols: (DFN8_3X2_PAD2_15X0_56_05-08-1702); tolerance: N/A
U22 = ICUSB331X: User Part Number: UPN; Tolerance: N/A; alternate symbols: (QFN24_4X4_PAD2_5X2_5); tolerance: N/A
U23 = ICMIC20X5: Tolerance: N/A; User Part Number: UPN; alternate symbols: (SO8); tolerance: N/A
U29 = ICTC7MBL3125: Tolerance: N/A; User Part Number: ***; alternate symbols: (TSSOP14); tolerance: N/A
Y1 = XTAL4PIN_V5: Tolerance: 20PPM; User Part Number: UPN; alternate symbols: (YSML126W98H31); tolerance: 20PPM
Y2 = XTALOSC4P_V2: Tolerance: N/A; User Part Number: UPN; alternate symbols: (YSML79W63H32); tolerance: N/A
Y4 = XTALOSC4P_V2: Tolerance: N/A; User Part Number: UPN; alternate symbols: (XSM4PL126W98H39); tolerance: N/A

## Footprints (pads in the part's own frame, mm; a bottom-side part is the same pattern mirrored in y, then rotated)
BGA24_8X6
  round 0.305 smd: A2(-2,-1) A3(-2,0) A4(-2,1) A5(-2,2) B1(-1,-2) B2(-1,-1) B3(-1,0) B4(-1,1) B5(-1,2) C1(0,-2) C2(0,-1) C3(0,0) C4(0,1) C5(0,2) D1(1,-2) D2(1,-1) D3(1,0) D4(1,1) D5(1,2) E1(2,-2) E2(2,-1) E3(2,0) E4(2,1) E5(2,2)
BGA153_13X11_50
  round 0.229 smd: A1(-3.25,-3.25) A2(-3.25,-2.75) A3(-3.25,-2.25) A4(-3.25,-1.75) A5(-3.25,-1.25) A6(-3.25,-0.75) A7(-3.25,-0.25) A8(-3.25,0.25) A9(-3.25,0.75) A10(-3.25,1.25) A11(-3.25,1.75) A12(-3.25,2.25) A13(-3.25,2.75) A14(-3.25,3.25) B1(-2.75,-3.25) B2(-2.75,-2.75) B3(-2.75,-2.25) B4(-2.75,-1.75) B5(-2.75,-1.25) B6(-2.75,-0.75) B7(-2.75,-0.25) B8(-2.75,0.25) B9(-2.75,0.75) B10(-2.75,1.25) B11(-2.75,1.75) B12(-2.75,2.25) B13(-2.75,2.75) B14(-2.75,3.25) C1(-2.25,-3.25) C2(-2.25,-2.75) C3(-2.25,-2.25) C4(-2.25,-1.75) C5(-2.25,-1.25) C6(-2.25,-0.75) C7(-2.25,-0.25) C8(-2.25,0.25) C9(-2.25,0.75) C10(-2.25,1.25) C11(-2.25,1.75) C12(-2.25,2.25) C13(-2.25,2.75) C14(-2.25,3.25) D1(-1.75,-3.25) D2(-1.75,-2.75) D3(-1.75,-2.25) D4(-1.75,-1.75) D12(-1.75,2.25) D13(-1.75,2.75) D14(-1.75,3.25) E1(-1.25,-3.25) E2(-1.25,-2.75) E3(-1.25,-2.25) E5(-1.25,-1.25) E6(-1.25,-0.75) E7(-1.25,-0.25) E8(-1.25,0.25) E9(-1.25,0.75) E10(-1.25,1.25) E12(-1.25,2.25) E13(-1.25,2.75) E14(-1.25,3.25) F1(-0.75,-3.25) F2(-0.75,-2.75) F3(-0.75,-2.25) F5(-0.75,-1.25) F10(-0.75,1.25) F12(-0.75,2.25) F13(-0.75,2.75) F14(-0.75,3.25) G1(-0.25,-3.25) G2(-0.25,-2.75) G3(-0.25,-2.25) G5(-0.25,-1.25) G10(-0.25,1.25) G12(-0.25,2.25) G13(-0.25,2.75) G14(-0.25,3.25) H1(0.25,-3.25) H2(0.25,-2.75) H3(0.25,-2.25) H5(0.25,-1.25) H10(0.25,1.25) H12(0.25,2.25) H13(0.25,2.75) H14(0.25,3.25) J1(0.75,-3.25) J2(0.75,-2.75) J3(0.75,-2.25) J5(0.75,-1.25) J10(0.75,1.25) J12(0.75,2.25) J13(0.75,2.75) J14(0.75,3.25) K1(1.25,-3.25) K2(1.25,-2.75) K3(1.25,-2.25) K5(1.25,-1.25) K6(1.25,-0.75) K7(1.25,-0.25) K8(1.25,0.25) K9(1.25,0.75) K10(1.25,1.25) K12(1.25,2.25) K13(1.25,2.75) K14(1.25,3.25) L1(1.75,-3.25) L2(1.75,-2.75) L3(1.75,-2.25) L12(1.75,2.25) L13(1.75,2.75) L14(1.75,3.25) M1(2.25,-3.25) M2(2.25,-2.75) M3(2.25,-2.25) M4(2.25,-1.75) M5(2.25,-1.25) M6(2.25,-0.75) M7(2.25,-0.25) M8(2.25,0.25) M9(2.25,0.75) M10(2.25,1.25) M11(2.25,1.75) M12(2.25,2.25) M13(2.25,2.75) M14(2.25,3.25) N1(2.75,-3.25) N2(2.75,-2.75) N3(2.75,-2.25) N4(2.75,-1.75) N5(2.75,-1.25) N6(2.75,-0.75) N7(2.75,-0.25) N8(2.75,0.25) N9(2.75,0.75) N10(2.75,1.25) N11(2.75,1.75) N12(2.75,2.25) N13(2.75,2.75) N14(2.75,3.25) P1(3.25,-3.25) P2(3.25,-2.75) P3(3.25,-2.25) P4(3.25,-1.75) P5(3.25,-1.25) P6(3.25,-0.75) P7(3.25,-0.25) P8(3.25,0.25) P9(3.25,0.75) P10(3.25,1.25) P11(3.25,1.75) P12(3.25,2.25) P13(3.25,2.75) P14(3.25,3.25)
BGA200_14_5X10H1_05
  round 0.356 smd: A1(-6.825,-4.4) A2(-6.825,-3.6) A3(-6.825,-2.8) A4(-6.825,-2) A5(-6.825,-1.2) A8(-6.825,1.2) A9(-6.825,2) A10(-6.825,2.8) A11(-6.825,3.6) A12(-6.825,4.4) AA1(6.175,-4.4) AA2(6.175,-3.6) AA3(6.175,-2.8) AA4(6.175,-2) AA5(6.175,-1.2) AA8(6.175,1.2) AA9(6.175,2) AA10(6.175,2.8) AA11(6.175,3.6) AA12(6.175,4.4) AB1(6.825,-4.4) AB2(6.825,-3.6) AB3(6.825,-2.8) AB4(6.825,-2) AB5(6.825,-1.2) AB8(6.825,1.2) AB9(6.825,2) AB10(6.825,2.8) AB11(6.825,3.6) AB12(6.825,4.4) B1(-6.175,-4.4) B2(-6.175,-3.6) B3(-6.175,-2.8) B4(-6.175,-2) B5(-6.175,-1.2) B8(-6.175,1.2) B9(-6.175,2) B10(-6.175,2.8) B11(-6.175,3.6) B12(-6.175,4.4) C1(-5.525,-4.4) C2(-5.525,-3.6) C3(-5.525,-2.8) C4(-5.525,-2) C5(-5.525,-1.2) C8(-5.525,1.2) C9(-5.525,2) C10(-5.525,2.8) C11(-5.525,3.6) C12(-5.525,4.4) D1(-4.875,-4.4) D2(-4.875,-3.6) D3(-4.875,-2.8) D4(-4.875,-2) D5(-4.875,-1.2) D8(-4.875,1.2) D9(-4.875,2) D10(-4.875,2.8) D11(-4.875,3.6) D12(-4.875,4.4) E1(-4.225,-4.4) E2(-4.225,-3.6) E3(-4.225,-2.8) E4(-4.225,-2) E5(-4.225,-1.2) E8(-4.225,1.2) E9(-4.225,2) E10(-4.225,2.8) E11(-4.225,3.6) E12(-4.225,4.4) F1(-3.575,-4.4) F2(-3.575,-3.6) F3(-3.575,-2.8) F4(-3.575,-2) F5(-3.575,-1.2) F8(-3.575,1.2) F9(-3.575,2) F10(-3.575,2.8) F11(-3.575,3.6) F12(-3.575,4.4) G1(-2.925,-4.4) G2(-2.925,-3.6) G3(-2.925,-2.8) G4(-2.925,-2) G5(-2.925,-1.2) G8(-2.925,1.2) G9(-2.925,2) G10(-2.925,2.8) G11(-2.925,3.6) G12(-2.925,4.4) H1(-2.275,-4.4) H2(-2.275,-3.6) H3(-2.275,-2.8) H4(-2.275,-2) H5(-2.275,-1.2) H8(-2.275,1.2) H9(-2.275,2) H10(-2.275,2.8) H11(-2.275,3.6) H12(-2.275,4.4) J1(-1.625,-4.4) J2(-1.625,-3.6) J3(-1.625,-2.8) J4(-1.625,-2) J5(-1.625,-1.2) J8(-1.625,1.2) J9(-1.625,2) J10(-1.625,2.8) J11(-1.625,3.6) J12(-1.625,4.4) K1(-0.975,-4.4) K2(-0.975,-3.6) K3(-0.975,-2.8) K4(-0.975,-2) K5(-0.975,-1.2) K8(-0.975,1.2) K9(-0.975,2) K10(-0.975,2.8) K11(-0.975,3.6) K12(-0.975,4.4) N1(0.975,-4.4) N2(0.975,-3.6) N3(0.975,-2.8) N4(0.975,-2) N5(0.975,-1.2) N8(0.975,1.2) N9(0.975,2) N10(0.975,2.8) N11(0.975,3.6) N12(0.975,4.4) P1(1.625,-4.4) P2(1.625,-3.6) P3(1.625,-2.8) P4(1.625,-2) P5(1.625,-1.2) P8(1.625,1.2) P9(1.625,2) P10(1.625,2.8) P11(1.625,3.6) P12(1.625,4.4) R1(2.275,-4.4) R2(2.275,-3.6) R3(2.275,-2.8) R4(2.275,-2) R5(2.275,-1.2) R8(2.275,1.2) R9(2.275,2) R10(2.275,2.8) R11(2.275,3.6) R12(2.275,4.4) T1(2.925,-4.4) T2(2.925,-3.6) T3(2.925,-2.8) T4(2.925,-2) T5(2.925,-1.2) T8(2.925,1.2) T9(2.925,2) T10(2.925,2.8) T11(2.925,3.6) T12(2.925,4.4) U1(3.575,-4.4) U2(3.575,-3.6) U3(3.575,-2.8) U4(3.575,-2) U5(3.575,-1.2) U8(3.575,1.2) U9(3.575,2) U10(3.575,2.8) U11(3.575,3.6) U12(3.575,4.4) V1(4.225,-4.4) V2(4.225,-3.6) V3(4.225,-2.8) V4(4.225,-2) V5(4.225,-1.2) V8(4.225,1.2) V9(4.225,2) V10(4.225,2.8) V11(4.225,3.6) V12(4.225,4.4) W1(4.875,-4.4) W2(4.875,-3.6) W3(4.875,-2.8) W4(4.875,-2) W5(4.875,-1.2) W8(4.875,1.2) W9(4.875,2) W10(4.875,2.8) W11(4.875,3.6) W12(4.875,4.4) Y1(5.525,-4.4) Y2(5.525,-3.6) Y3(5.525,-2.8) Y4(5.525,-2) Y5(5.525,-1.2) Y8(5.525,1.2) Y9(5.525,2) Y10(5.525,2.8) Y11(5.525,3.6) Y12(5.525,4.4)
BGA484_18X18
  round 0.356 smd: A1(-8.4,-8.4) A2(-8.4,-7.6) A3(-8.4,-6.8) A4(-8.4,-6) A5(-8.4,-5.2) A6(-8.4,-4.4) A7(-8.4,-3.6) A8(-8.4,-2.8) A9(-8.4,-2) A10(-8.4,-1.2) A11(-8.4,-0.4) A12(-8.4,0.4) A13(-8.4,1.2) A14(-8.4,2) A15(-8.4,2.8) A16(-8.4,3.6) A17(-8.4,4.4) A18(-8.4,5.2) A19(-8.4,6) A20(-8.4,6.8) A21(-8.4,7.6) A22(-8.4,8.4) AA1(7.6,-8.4) AA2(7.6,-7.6) AA3(7.6,-6.8) AA4(7.6,-6) AA5(7.6,-5.2) AA6(7.6,-4.4) AA7(7.6,-3.6) AA8(7.6,-2.8) AA9(7.6,-2) AA10(7.6,-1.2) AA11(7.6,-0.4) AA12(7.6,0.4) AA13(7.6,1.2) AA14(7.6,2) AA15(7.6,2.8) AA16(7.6,3.6) AA17(7.6,4.4) AA18(7.6,5.2) AA19(7.6,6) AA20(7.6,6.8) AA21(7.6,7.6) AA22(7.6,8.4) AB1(8.4,-8.4) AB2(8.4,-7.6) AB3(8.4,-6.8) AB4(8.4,-6) AB5(8.4,-5.2) AB6(8.4,-4.4) AB7(8.4,-3.6) AB8(8.4,-2.8) AB9(8.4,-2) AB10(8.4,-1.2) AB11(8.4,-0.4) AB12(8.4,0.4) AB13(8.4,1.2) AB14(8.4,2) AB15(8.4,2.8) AB16(8.4,3.6) AB17(8.4,4.4) AB18(8.4,5.2) AB19(8.4,6) AB20(8.4,6.8) AB21(8.4,7.6) AB22(8.4,8.4) B1(-7.6,-8.4) B2(-7.6,-7.6) B3(-7.6,-6.8) B4(-7.6,-6) B5(-7.6,-5.2) B6(-7.6,-4.4) B7(-7.6,-3.6) B8(-7.6,-2.8) B9(-7.6,-2) B10(-7.6,-1.2) B11(-7.6,-0.4) B12(-7.6,0.4) B13(-7.6,1.2) B14(-7.6,2) B15(-7.6,2.8) B16(-7.6,3.6) B17(-7.6,4.4) B18(-7.6,5.2) B19(-7.6,6) B20(-7.6,6.8) B21(-7.6,7.6) B22(-7.6,8.4) C1(-6.8,-8.4) C2(-6.8,-7.6) C3(-6.8,-6.8) C4(-6.8,-6) C5(-6.8,-5.2) C6(-6.8,-4.4) C7(-6.8,-3.6) C8(-6.8,-2.8) C9(-6.8,-2) C10(-6.8,-1.2) C11(-6.8,-0.4) C12(-6.8,0.4) C13(-6.8,1.2) C14(-6.8,2) C15(-6.8,2.8) C16(-6.8,3.6) C17(-6.8,4.4) C18(-6.8,5.2) C19(-6.8,6) C20(-6.8,6.8) C21(-6.8,7.6) C22(-6.8,8.4) D1(-6,-8.4) D2(-6,-7.6) D3(-6,-6.8) D4(-6,-6) D5(-6,-5.2) D6(-6,-4.4) D7(-6,-3.6) D8(-6,-2.8) D9(-6,-2) D10(-6,-1.2) D11(-6,-0.4) D12(-6,0.4) D13(-6,1.2) D14(-6,2) D15(-6,2.8) D16(-6,3.6) D17(-6,4.4) D18(-6,5.2) D19(-6,6) D20(-6,6.8) D21(-6,7.6) D22(-6,8.4) E1(-5.2,-8.4) E2(-5.2,-7.6) E3(-5.2,-6.8) E4(-5.2,-6) E5(-5.2,-5.2) E6(-5.2,-4.4) E7(-5.2,-3.6) E8(-5.2,-2.8) E9(-5.2,-2) E10(-5.2,-1.2) E11(-5.2,-0.4) E12(-5.2,0.4) E13(-5.2,1.2) E14(-5.2,2) E15(-5.2,2.8) E16(-5.2,3.6) E17(-5.2,4.4) E18(-5.2,5.2) E19(-5.2,6) E20(-5.2,6.8) E21(-5.2,7.6) E22(-5.2,8.4) F1(-4.4,-8.4) F2(-4.4,-7.6) F3(-4.4,-6.8) F4(-4.4,-6) F5(-4.4,-5.2) F6(-4.4,-4.4) F7(-4.4,-3.6) F8(-4.4,-2.8) F9(-4.4,-2) F10(-4.4,-1.2) F11(-4.4,-0.4) F12(-4.4,0.4) F13(-4.4,1.2) F14(-4.4,2) F15(-4.4,2.8) F16(-4.4,3.6) F17(-4.4,4.4) F18(-4.4,5.2) F19(-4.4,6) F20(-4.4,6.8) F21(-4.4,7.6) F22(-4.4,8.4) G1(-3.6,-8.4) G2(-3.6,-7.6) G3(-3.6,-6.8) G4(-3.6,-6) G5(-3.6,-5.2) G6(-3.6,-4.4) G7(-3.6,-3.6) G8(-3.6,-2.8) G9(-3.6,-2) G10(-3.6,-1.2) G11(-3.6,-0.4) G12(-3.6,0.4) G13(-3.6,1.2) G14(-3.6,2) G15(-3.6,2.8) G16(-3.6,3.6) G17(-3.6,4.4) G18(-3.6,5.2) G19(-3.6,6) G20(-3.6,6.8) G21(-3.6,7.6) G22(-3.6,8.4) H1(-2.8,-8.4) H2(-2.8,-7.6) H3(-2.8,-6.8) H4(-2.8,-6) H5(-2.8,-5.2) H6(-2.8,-4.4) H7(-2.8,-3.6) H8(-2.8,-2.8) H9(-2.8,-2) H10(-2.8,-1.2) H11(-2.8,-0.4) H12(-2.8,0.4) H13(-2.8,1.2) H14(-2.8,2) H15(-2.8,2.8) H16(-2.8,3.6) H17(-2.8,4.4) H18(-2.8,5.2) H19(-2.8,6) H20(-2.8,6.8) H21(-2.8,7.6) H22(-2.8,8.4) J1(-2,-8.4) J2(-2,-7.6) J3(-2,-6.8) J4(-2,-6) J5(-2,-5.2) J6(-2,-4.4) J7(-2,-3.6) J8(-2,-2.8) J9(-2,-2) J10(-2,-1.2) J11(-2,-0.4) J12(-2,0.4) J13(-2,1.2) J14(-2,2) J15(-2,2.8) J16(-2,3.6) J17(-2,4.4) J18(-2,5.2) J19(-2,6) J20(-2,6.8) J21(-2,7.6) J22(-2,8.4) K1(-1.2,-8.4) K2(-1.2,-7.6) K3(-1.2,-6.8) K4(-1.2,-6) K5(-1.2,-5.2) K6(-1.2,-4.4) K7(-1.2,-3.6) K8(-1.2,-2.8) K9(-1.2,-2) K10(-1.2,-1.2) K11(-1.2,-0.4) K12(-1.2,0.4) K13(-1.2,1.2) K14(-1.2,2) K15(-1.2,2.8) K16(-1.2,3.6) K17(-1.2,4.4) K18(-1.2,5.2) K19(-1.2,6) K20(-1.2,6.8) K21(-1.2,7.6) K22(-1.2,8.4) L1(-0.4,-8.4) L2(-0.4,-7.6) L3(-0.4,-6.8) L4(-0.4,-6) L5(-0.4,-5.2) L6(-0.4,-4.4) L7(-0.4,-3.6) L8(-0.4,-2.8) L9(-0.4,-2) L10(-0.4,-1.2) L11(-0.4,-0.4) L12(-0.4,0.4) L13(-0.4,1.2) L14(-0.4,2) L15(-0.4,2.8) L16(-0.4,3.6) L17(-0.4,4.4) L18(-0.4,5.2) L19(-0.4,6) L20(-0.4,6.8) L21(-0.4,7.6) L22(-0.4,8.4) M1(0.4,-8.4) M2(0.4,-7.6) M3(0.4,-6.8) M4(0.4,-6) M5(0.4,-5.2) M6(0.4,-4.4) M7(0.4,-3.6) M8(0.4,-2.8) M9(0.4,-2) M10(0.4,-1.2) M11(0.4,-0.4) M12(0.4,0.4) M13(0.4,1.2) M14(0.4,2) M15(0.4,2.8) M16(0.4,3.6) M17(0.4,4.4) M18(0.4,5.2) M19(0.4,6) M20(0.4,6.8) M21(0.4,7.6) M22(0.4,8.4) N1(1.2,-8.4) N2(1.2,-7.6) N3(1.2,-6.8) N4(1.2,-6) N5(1.2,-5.2) N6(1.2,-4.4) N7(1.2,-3.6) N8(1.2,-2.8) N9(1.2,-2) N10(1.2,-1.2) N11(1.2,-0.4) N12(1.2,0.4) N13(1.2,1.2) N14(1.2,2) N15(1.2,2.8) N16(1.2,3.6) N17(1.2,4.4) N18(1.2,5.2) N19(1.2,6) N20(1.2,6.8) N21(1.2,7.6) N22(1.2,8.4) P1(2,-8.4) P2(2,-7.6) P3(2,-6.8) P4(2,-6) P5(2,-5.2) P6(2,-4.4) P7(2,-3.6) P8(2,-2.8) P9(2,-2) P10(2,-1.2) P11(2,-0.4) P12(2,0.4) P13(2,1.2) P14(2,2) P15(2,2.8) P16(2,3.6) P17(2,4.4) P18(2,5.2) P19(2,6) P20(2,6.8) P21(2,7.6) P22(2,8.4) R1(2.8,-8.4) R2(2.8,-7.6) R3(2.8,-6.8) R4(2.8,-6) R5(2.8,-5.2) R6(2.8,-4.4) R7(2.8,-3.6) R8(2.8,-2.8) R9(2.8,-2) R10(2.8,-1.2) R11(2.8,-0.4) R12(2.8,0.4) R13(2.8,1.2) R14(2.8,2) R15(2.8,2.8) R16(2.8,3.6) R17(2.8,4.4) R18(2.8,5.2) R19(2.8,6) R20(2.8,6.8) R21(2.8,7.6) R22(2.8,8.4) T1(3.6,-8.4) T2(3.6,-7.6) T3(3.6,-6.8) T4(3.6,-6) T5(3.6,-5.2) T6(3.6,-4.4) T7(3.6,-3.6) T8(3.6,-2.8) T9(3.6,-2) T10(3.6,-1.2) T11(3.6,-0.4) T12(3.6,0.4) T13(3.6,1.2) T14(3.6,2) T15(3.6,2.8) T16(3.6,3.6) T17(3.6,4.4) T18(3.6,5.2) T19(3.6,6) T20(3.6,6.8) T21(3.6,7.6) T22(3.6,8.4) U1(4.4,-8.4) U2(4.4,-7.6) U3(4.4,-6.8) U4(4.4,-6) U5(4.4,-5.2) U6(4.4,-4.4) U7(4.4,-3.6) U8(4.4,-2.8) U9(4.4,-2) U10(4.4,-1.2) U11(4.4,-0.4) U12(4.4,0.4) U13(4.4,1.2) U14(4.4,2) U15(4.4,2.8) U16(4.4,3.6) U17(4.4,4.4) U18(4.4,5.2) U19(4.4,6) U20(4.4,6.8) U21(4.4,7.6) U22(4.4,8.4) V1(5.2,-8.4) V2(5.2,-7.6) V3(5.2,-6.8) V4(5.2,-6) V5(5.2,-5.2) V6(5.2,-4.4) V7(5.2,-3.6) V8(5.2,-2.8) V9(5.2,-2) V10(5.2,-1.2) V11(5.2,-0.4) V12(5.2,0.4) V13(5.2,1.2) V14(5.2,2) V15(5.2,2.8) V16(5.2,3.6) V17(5.2,4.4) V18(5.2,5.2) V19(5.2,6) V20(5.2,6.8) V21(5.2,7.6) V22(5.2,8.4) W1(6,-8.4) W2(6,-7.6) W3(6,-6.8) W4(6,-6) W5(6,-5.2) W6(6,-4.4) W7(6,-3.6) W8(6,-2.8) W9(6,-2) W10(6,-1.2) W11(6,-0.4) W12(6,0.4) W13(6,1.2) W14(6,2) W15(6,2.8) W16(6,3.6) W17(6,4.4) W18(6,5.2) W19(6,6) W20(6,6.8) W21(6,7.6) W22(6,8.4) Y1(6.8,-8.4) Y2(6.8,-7.6) Y3(6.8,-6.8) Y4(6.8,-6) Y5(6.8,-5.2) Y6(6.8,-4.4) Y7(6.8,-3.6) Y8(6.8,-2.8) Y9(6.8,-2) Y10(6.8,-1.2) Y11(6.8,-0.4) Y12(6.8,0.4) Y13(6.8,1.2) Y14(6.8,2) Y15(6.8,2.8) Y16(6.8,3.6) Y17(6.8,4.4) Y18(6.8,5.2) Y19(6.8,6) Y20(6.8,6.8) Y21(6.8,7.6) Y22(6.8,8.4)
C0201
  rect 0.305x0.406 smd: 1(-0.318,0) 2(0.318,0)
C0402
  rect 0.584x0.66 smd: 1(-0.5,0) 2(0.5,0)
C0603
  rect 0.94x0.991 smd: 1(-0.8,0) 2(0.8,0)
C0805
  rect 1.143x1.448 smd: 1(-0.9,0) 2(0.9,0)
C0805H53
  rect 1.295x1.6 smd: 1(-0.953,0) 2(0.953,0)
C0805H55
  rect 1.143x1.448 smd: 1(-0.9,0) 2(0.9,0)
C0805H60
  rect 1.295x1.6 smd: 1(-0.953,0) 2(0.953,0)
C1206H71
  rect 1.6x2.007 smd: 1(-1.397,0) 2(1.397,0)
